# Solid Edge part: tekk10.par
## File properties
Author: Mac
Template: Normal.par
Last saved by: Mac
Revision: 42
Application: Solid Edge
Material: Epoxy, cast rigid
Face Style: White
Fill Style: ANSI34(Plastic)
Virtual Style: Shiny resin yellow
Coef. of Thermal Exp: 5.9e-05
Thermal Conductivity: 2.1
Specific Heat: 0.0
Modulus of Elasticity: 3102640650.0
Poission's Ratio: 0.37
Yield Stress: 65500191.5
Ultimate Stress: 0.0
Elongation: 0.0
Density: 1300,000 kg/m^3
Accuracy: 0,990
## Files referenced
..\Asm5.asm
AC:\Documents and Settings\Mac\Desktop\paat\Abi\paat abi1\Asm5.asm
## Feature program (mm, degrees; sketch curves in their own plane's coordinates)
sketch for "unnamed Protrusion 1" plane through (0, 0, 0) normal (0, 0, 1) x-axis (1, 0, 0)
  arc centre (-94.797, 27.5681) radius 7 from (-95.0745, 34.5626) to (-101.6037, 29.2016) ccw
  arc centre (18.0006, 0.4998) radius 123 from (-101.6037, 29.2016) to (-104.9983, 0) ccw
  line (105.0005, 0) -> (-104.9983, 0)
  line (105.0005, 0) -> (105.0005, 0.5)
extrude "unnamed Protrusion 1" add finite 5 along +normal
draft "Draft_6"  Angles1 = 15 deg
sketch for "ExtrudedProtrusion_6" plane through (0.0006, 17.2144, 5) normal (0, 0, 1) x-axis (1, 0, 0)
  line (-56.4794, 11.396) -> (-56.4794, 5.396)
  line (-56.5794, 5.396) -> (-56.4794, 5.396)
  line (-56.5794, 5.396) -> (-56.5794, 10.595)
  bspline degree 3 poles (-56.5794, 10.595) (-69.5519, 10.4638) (-83.3133, 10.0955) (-97.8592, 9.4888) knots 0 1 multiplicities 4 4
  arc centre (-97.8325, 8.8489) radius 0.6404 from (-97.8592, 9.4888) to (-98.4578, 8.9869) ccw
  arc centre (18.0001, -16.7146) radius 119.2603 from (-98.4578, 8.9869) to (-98.8901, 6.9432) ccw
  line (-98.8901, 6.9432) -> (-98.8901, -17.2144)
  line (-98.8901, -17.2144) -> (-100.2901, -17.2144)
  line (-100.2901, 7.083) -> (-100.2901, -17.2144)
  arc centre (18.0001, -16.7146) radius 120.6603 from (-99.8249, 9.2886) to (-100.2901, 7.083) ccw
  arc centre (-97.8325, 8.8489) radius 2.0404 from (-97.9175, 10.8875) to (-99.8249, 9.2886) ccw
  bspline degree 3 poles (32.7696, 7.7049) (18.6993, 9.6016) (2.4867, 10.8876) (-15.8311, 11.5412) (-39.6424, 12.3909) (-67.0155, 12.1765) (-97.9175, 10.8875) knots 0 0.9628 1 multiplicities 4 3 4
  bspline degree 3 poles (32.7696, 7.7049) (35.932, 0.931) (37.7314, -7.3754) (38.1682, -17.2144) knots 0 1 multiplicities 4 4
  line (38.1682, -17.2144) -> (10.8739, -17.2144)
  line (10.8739, 9.4225) -> (10.8739, -17.2144)
  bspline degree 3 poles (10.8739, 9.4225) (2.5339, 10.0961) (-6.3768, 10.6036) (-15.8526, 10.9417) (-28.4038, 11.3895) (-41.9478, 11.5415) (-56.4794, 11.396) knots 0 0.3128 1 multiplicities 4 3 4
extrude "ExtrudedProtrusion_6" add finite 1.4 along +normal
sketch for "unnamed Protrusion 2" plane through (-100.19, 0, 0) normal (1, 0, 0) x-axis (0, 1, 0)
  line (0.5, 0) -> (0.5, -11.1711)
  line (0.5, -11.1711) -> (24, -11.1711)
  line (24, -11.1711) -> (24, 0)
  line (24, 0) -> (0.5, 0)
extrude "unnamed Protrusion 2" add along +normal
sketch for "unnamed Protrusion 3" plane through (0, 0, 0) normal (0, -1, 0) x-axis (1, 0, 0)
  line (-100.19, 0) -> (-104.9994, 0)
  line (-100.19, -11.1711) -> (-110.0363, -11.1711)
  line (-100.19, 0) -> (-100.19, -11.1711)
extrude "unnamed Protrusion 3" add to key point along -normal
sketch for "ExtrudedProtrusion_13" plane through (0, 0, 0) normal (0, 0, 1) x-axis (1, 0, 0)
  arc centre (18.3803, 0.3808) radius 124.3034 from (-103.6585, 24) to (-102.7729, 28.1879) cw
  arc centre (-94.797, 27.5681) radius 8 from (-102.7729, 28.1879) to (-95.1142, 35.5618) cw
  arc centre (105.0005, 0) radius 1.2274 from (106.0979, 0.5496) to (106.2279, 0) cw
  line (106.2279, 0) -> (-99.6166, 0)
  line (-99.6166, 24) -> (-99.6166, 0)
  line (-99.6166, 24) -> (-103.6585, 24)
extrude "ExtrudedProtrusion_13" add finite 0.1 along +normal
sketch for "ExtrudedCutout_2" plane through (0, 0, 0) normal (0, -1, 0) x-axis (1, 0, 0)
  line (-109.752, 5) -> (-100.2896, 5)
  bspline degree 3 poles (-100.2896, 5) (-101.041, -0.6512) (-100.842, -5.6753) (-101.0728, -10.0711) knots 0 1 multiplicities 4 4
  line (-109.752, -10.0711) -> (-101.0728, -10.0711)
  line (-109.752, -10.0711) -> (-109.752, 5)
extrude "ExtrudedCutout_2" cut finite 22.9 along -normal
sketch for "ExtrudedProtrusion_16" plane through (-31.0604, 14.749, 6.4) normal (0, 0, 1) x-axis (0, 1, 0)
  bspline degree 3 poles (12.6794, 45.7982) (12.8671, 38.837) (12.994, 32.0769) (13.0603, 25.5184) knots 0 1 multiplicities 4 4
  line (13.0603, 25.5184) -> (7.8613, 25.5184)
  line (7.8613, 25.5184) -> (7.8613, 25.4184)
  line (7.8613, 25.4184) -> (13.8614, 25.4184)
  line (11.8878, -41.9348) -> (-14.749, -41.9348)
  line (-14.749, -41.9348) -> (-14.749, -69.2292)
  bspline degree 3 poles (10.0625, -63.8806) (11.9634, -49.7998) (13.2521, -33.569) (13.9066, -15.2263) (14.5579, 3.0262) (14.5839, 23.3727) (13.9798, 45.7982) knots 0 0.9746 1 multiplicities 4 3 4
  line (13.9798, 45.7982) -> (12.6794, 45.7982)
extrude "ExtrudedProtrusion_16" add finite 4 along +normal
draft "Draft_15"  Angles1 = 5 deg
draft "Draft_16"  Angles1 = 30 deg
lofted protrusion "unnamed LoftedProtrusion 1"
sketch for "unnamed Cutout 1" plane through (0, 0, 0) normal (0, 0, 1) x-axis (1, 0, 0)
  line (18.9219, 0) -> (82.9588, 0)
  line (82.9588, 0) -> (82.9588, -19.7583)
  line (18.9219, -19.7583) -> (82.9588, -19.7583)
  line (18.9219, 0) -> (18.9219, -19.7583)
extrude "unnamed Cutout 1" cut to key point along +normal
fillet "Round_5" radius 3.5
sketch for "unnamed Cutout 2" plane through (74.0361, 3, 6.9827) normal (0.330445, 0, 0.943825) x-axis (0.943825, 0, -0.330445)
extrude "unnamed Cutout 2" cut through along +normal
fillet "Round_6" radius 0.1
sketch for "ExtrudedProtrusion_17" plane through (-15.4502, 14.5146, 10.4) normal (0, 0, 1) x-axis (1, 0, 0)
extrude "ExtrudedProtrusion_17" add finite 1 along +normal
swept cutout "unnamed SweptCutout 1"
thinwall "unnamed Thinwall 1"
sketch for "unnamed Cutout 3" plane through (74.0588, 2.45, 6.9747) normal (0.330445, 0, 0.943825) x-axis (0.943825, 0, -0.330445)
extrude "unnamed Cutout 3" cut through along -normal
sketch for "ExtrudedProtrusion_18" plane through (-44.0075, 14.5811, 4.9) normal (0, 0, -1) x-axis (1, 0, 0)
extrude "ExtrudedProtrusion_18" add finite 11 along +normal
thinwall "unnamed Thinwall 2"
sketch for "unnamed Cutout 4" plane through (1.0405, 17.2144, 5) normal (0, 0, 1) x-axis (-1, 0, 0)
extrude "unnamed Cutout 4" cut through along -normal
sketch for "unnamed Protrusion 4" plane through (-56.5288, 25.2103, 5) normal (0, 0, -1) x-axis (0, 1, 0)
extrude "unnamed Protrusion 4" add along +normal
sketch for "unnamed Cutout 5" plane through (-44.0075, 14.806, -6) normal (0, 0, 1) x-axis (1, 0, 0)
extrude "unnamed Cutout 5" cut through along -normal
sketch for "unnamed Cutout 6" plane through (10.9745, 13.367, 2.6) normal (1, 0, 0) x-axis (0, 1, 0)
  line (15.0172, -8.7) -> (-14.9724, -8.7)
  line (-14.9724, 2.3) -> (-14.9724, -8.7)
  line (14.9833, 2.3) -> (-14.9724, 2.3)
  bspline degree 3 poles (14.9833, 2.3) (14.995, -1.3667) (15.0062, -5.0333) (15.0172, -8.7) knots 0 1 multiplicities 4 4
extrude "unnamed Cutout 6" cut along +normal
sketch for "unnamed Cutout 7" plane through (-8.4912, 14.3643, 11.4) normal (0, 0, 1) x-axis (1, 0, 0)
extrude "unnamed Cutout 7" cut to key point along -normal
body pattern "unnamed BodyPattern 1"
pattern "unnamed Pattern 1"
sketch for "unnamed Protrusion 5" plane through (-98.8896, 10.8081, 0.2) normal (1, 0, 0) x-axis (0, 1, 0)
extrude "unnamed Protrusion 5" add to key point along -normal
sketch for "unnamed Cutout 8" plane through (-98.8896, 0, 0.2) normal (1, 0, 0) x-axis (0, 0, -1)
extrude "unnamed Cutout 8" cut through along -normal
sketch for "ExtrudedCutout_20" plane through (0, 0, 0) normal (0, -1, 0) x-axis (1, 0, 0)
extrude "ExtrudedCutout_20" cut finite 16.0415 along +normal
fillet "Round_8" radius 0.1
sketch for "unnamed Cutout 9" plane through (-98.8896, -7, -6.15) normal (1, 0, 0) x-axis (0, -1, 0)
extrude "unnamed Cutout 9" cut to key point along -normal
thinwall "Thinwall_35"  Thickness = 0.1 mm
"unnamed Protrusion 6" has 27 sketches; the first 24 follow
sketch for "unnamed Protrusion 6" #1 plane through (-56.5788, 28.6678, 10.3) normal (-0.017704, 0.994034, 0.107628) x-axis (-0.982002, 0.002957, -0.188848)
extrude "unnamed Protrusion 6" add along -normal
"unnamed Protrusion 7" has 27 sketches; the first 24 follow
sketch for "unnamed Protrusion 7" #1 plane through (-76.8586, -28.7288, 6.4) normal (-0.012228, -0.996776, 0.079301) x-axis (0.981092, 0.003359, 0.193511)
extrude "unnamed Protrusion 7" add along -normal
sketch for "ExtrudedCutout_22" #1 plane through (-53.9233, 0, -6) normal (0, 0, 1) x-axis (0, 1, 0)
sketch for "ExtrudedCutout_22" #2 plane through (-53.9233, 0, -6) normal (0, 0, 1) x-axis (0, 1, 0)
sketch for "ExtrudedCutout_22" #3 plane through (-53.9233, 0, -6) normal (0, 0, 1) x-axis (0, 1, 0)
extrude "ExtrudedCutout_22" cut finite 0.01 along -normal
Other named dimensions: "KeypointCurve_10": StartDerivMagnitude = -43.6142 mm; EndDerivMagnitude = 43.6142 mm | "OffsetSurface_1": Distance = 0.1 mm | "ExtrudedSurface_1": FiniteDepth = 6 mm | "ExtrudedSurface_9": FiniteDepth = 85.0968 mm | "OffsetSurface_2": Distance = 0.01 mm | "OffsetSurface_3": Distance = 0.01 mm
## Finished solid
Body 1: sheet body, 1 face, 4 edges, 4 vertices.
  Faces by surface: offset 1
  Edges by curve: curve on surface 4
Body 2: sheet body, 1 face, 4 edges, 4 vertices.
  Faces by surface: offset 1
  Edges by curve: curve on surface 4
Body 3: sheet body, 1 face, 4 edges, 4 vertices.
  Faces by surface: plane 1
  Edges by curve: line 4
Body 4: sheet body, 1 face, 4 edges, 4 vertices.
  Faces by surface: plane 1
  Edges by curve: line 4
Body 5: sheet body, 1 face, 4 edges, 4 vertices.
  Faces by surface: offset 1
  Edges by curve: curve on surface 4
Body 6: sheet body, 1 face, 4 edges, 4 vertices.
  Faces by surface: spline 1
  Edges by curve: spline 3, circle 1
Body 7: solid body, 901 faces, 2466 edges, 1629 vertices.
  Faces by surface: plane 457, swept 261, offset 79, cylinder 50, blend 24, spline 22, cone 8
  Edges by curve: intersection 1286, line 972, circle 108, spline 56, curve on surface 32, ellipse 12
Bounding box of the edges (mm; curved faces can reach further): 218.616 x 85.097 x 51.944, from (-112.3877, -42.5484, -36.2684) to (106.2279, 42.5484, 15.6751).
Cylindrical faces by radius (mm): R0.08 x6, R0.1 x15, R0.2 x8, R0.6404 x2, R0.7404 x2, R1.2274 x1, R1.9404 x2, R2.0404 x2, R8 x2, R119.2603 x2, R119.3603 x2, R120.5603 x2, R120.6603 x2, R124.3034 x2
Conical faces (half-angle, radius in mm at the cone's reference point): 15 deg R6.9034 x2, 15 deg R7 x2, 15 deg R122.9034 x2, 15 deg R123 x2
Planar faces by outward normal: +x 14, +y 10, +z 13, -x 15, -y 13, -z 13, oblique 379
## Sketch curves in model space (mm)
line (42.4934, 0.0256, 11.4) -> (39.6089, -0.2079, 11.4)
line (42.4934, 0.0256, 11.4) -> (42.4934, 0.0256, 10.4)
line (42.4934, 0.0256, 10.4) -> (40.7983, -0.1116, 10.4)
arc centre (-47.5053, -7.2589, -94.1029) radius 137.0017 from (40.7983, -0.1116, 10.4) through (40.205, -0.1596, 10.9017) to (39.6089, -0.2079, 11.4)
line (-7.0908, 0, -7.0432) -> (-5.1033, 0, 15.6751)
spline (99.31, 7.1, 2.55) -> (36.2531, 30.1455, 2.55) -> (-56.5831, 34.8661, 2.55)
spline (39.8441, -0.1888, 11.4) -> (36.7349, 14.4668, 11.4) -> (30.3607, 24.681, 11.4)
line (-86.4757, 0, -12.1697) -> (102.5777, 0, -23.8321)
line (84.448, 0, 42.5362) -> (77.6507, 0, -43.2576)
line (-21.5, 0, 50.9303) -> (-28.2973, 0, -34.8635)
line (79.6991, 0, 5) -> (68.3732, 0, 8.9653)
arc centre (69.4492, -4.3, 8.5886) radius 0.2 from (69.4492, -4.5, 8.5886) through (69.3119, -4.4372, 8.6367) to (69.2604, -4.3, 8.6547)
line (77.6848, -4.5, 5.7052) -> (69.4492, -4.5, 8.5886)
arc centre (77.6848, -4.3, 5.7052) radius 0.2 from (77.8736, -4.3, 5.6391) through (77.8143, -4.4455, 5.6599) to (77.6848, -4.5, 5.7052)
line (77.8736, -4.3, 5.6391) -> (77.8736, 4.3, 5.6391)
arc centre (77.6848, 4.3, 5.7052) radius 0.2 from (77.8736, 4.3, 5.6391) through (77.8143, 4.4455, 5.6599) to (77.6848, 4.5, 5.7052)
line (77.6848, 4.5, 5.7052) -> (69.4492, 4.5, 8.5886)
arc centre (69.4492, 4.3, 8.5886) radius 0.2 from (69.4492, 4.5, 8.5886) through (69.3119, 4.4372, 8.6367) to (69.2604, 4.3, 8.6547)
line (69.2604, 4.3, 8.6547) -> (69.2604, -4.3, 8.6547)
spline (79.6991, 0, 5) -> (68.5758, -0.2796, 8.9354) -> (37.2044, -1.068, 10.4)
line (37.2044, -1.068, 10.4) -> (37.2044, -1.068, 5)
line (37.2044, -1.068, 5) -> (79.6991, 0, 5)
line (32.7701, 24.9192, 6.4) -> (32.7701, 24.9192, 5)
spline (32.7701, 24.9192, 5) -> (32.2097, 21.3193, 9.2031) -> (29.5886, 4.4839, 10.373)
line (29.5886, 4.4839, 10.373) -> (29.5886, 4.4839, 5)
line (32.7701, 24.9192, 5) -> (29.5886, 4.4839, 5)
spline (32.7701, 24.9192, 5) -> (65.0356, 16.1294, 5) -> (79.6991, 0, 5)
line (106.2279, 0, 0) -> (-99.6166, 0, 0)
arc centre (105.0005, 0, 0) radius 1.2274 from (106.0979, 0.5496, 0) through (106.1949, 0.2824, 0) to (106.2279, 0, 0)
spline (-95.1142, 35.5618, 0) -> (30.0728, 32.6689, 0) -> (106.0979, 0.5496, 0)
arc centre (-94.797, 27.5681, 0) radius 8 from (-102.7729, 28.1879, 0) through (-100.1758, 33.49, 0) to (-95.1142, 35.5618, 0)
arc centre (18.3803, 0.3808, 0) radius 124.3034 from (-103.6585, 24, 0) through (-103.2338, 26.0978, 0) to (-102.7729, 28.1879, 0)
line (-99.6166, 24, 0) -> (-103.6585, 24, 0)
line (-99.6166, 24, 0) -> (-99.6166, 0, 0)
line (-100.19, 23, -0.0414) -> (-100.19, 23, -10.1711)
spline (-100.19, 24, -0.0404) -> (-100.19, 23.5002, -0.0409) -> (-100.19, 23, -0.0414)
line (-100.19, 24, -11.1711) -> (-100.19, 24, -0.0404)
line (-100.19, 0.5, -11.1711) -> (-100.19, 24, -11.1711)
line (-100.19, 0.5, -10.1711) -> (-100.19, 0.5, -11.1711)
line (-100.19, 0.5, -10.1711) -> (-100.19, 23, -10.1711)
line (-100.19, 24, -11.1711) -> (-100.19, 24, 0)
line (-100.19, 24, 0) -> (-100.19, 0.5, 0)
line (-100.19, 0.5, 0) -> (-100.19, 0.5, -11.1711)
line (-100.19, 0.5, -11.1711) -> (-100.19, 24, -11.1711)
line (10.8745, 26.6368, 5) -> (10.8745, 0, 5)
spline (10.8745, 26.6368, 5) -> (-26.3292, 28.4561, 5) -> (-56.4788, 28.6104, 5)
line (-56.4788, 28.6104, 5) -> (-56.4788, 22.6104, 5)
line (-56.5788, 22.6104, 5) -> (-56.4788, 22.6104, 5)
line (-56.5788, 22.6104, 5) -> (-56.5788, 27.8093, 5)
spline (-56.5788, 27.8093, 5) -> (-76.6287, 27.4346, 5) -> (-97.8586, 26.7031, 5)
arc centre (-97.8319, 26.0633, 5) radius 0.6404 from (-97.8586, 26.7031, 5) through (-98.2433, 26.5541, 5) to (-98.4572, 26.2013, 5)
arc centre (18.0006, 0.4998, 5) radius 119.2603 from (-98.4572, 26.2013, 5) through (-98.6779, 25.1804, 5) to (-98.8896, 24.1575, 5)
line (-98.8896, 24.1575, 5) -> (-98.8896, 0, 5)
line (-98.8896, 0, 5) -> (-100.2896, 0, 5)
line (-100.2896, 24.2974, 5) -> (-100.2896, 0, 5)
arc centre (18.0006, 0.4998, 5) radius 120.6603 from (-99.8243, 26.503, 5) through (-100.0621, 25.4013, 5) to (-100.2896, 24.2974, 5)
arc centre (-97.8319, 26.0633, 5) radius 2.0404 from (-97.9169, 28.1019, 5) through (-99.1427, 27.627, 5) to (-99.8243, 26.503, 5)
spline (32.7701, 24.9192, 5) -> (9.1204, 27.3772, 5) -> (-97.9169, 28.1019, 5)
spline (32.7701, 24.9192, 5) -> (36.4915, 13.609, 5) -> (38.1688, 0, 5)
line (38.1688, 0, 5) -> (10.8745, 0, 5)
spline (-110.7878, 30.7782, -24.5324) -> (-28.564, 29.4368, -24.5324) -> (52.4813, 16.4919, -24.5324)
spline (-104.9994, 0.5, 0) -> (-110.542, 0.5, -13.4256) -> (-112.3877, 0.5, -36.2684)
arc centre (18.0006, 0.4998, 0) radius 123 from (-101.6037, 29.2016, 0) through (-104.1475, 14.9509, 0) to (-104.9994, 0.5, 0)
line (105.0005, 0, 0) -> (-104.9983, 0, 0)
line (105.0005, 0, 0) -> (105.0005, 0.5, 0)
spline (105.0005, 0.5, 0) -> (44.2326, 29.5896, 0) -> (-95.0745, 34.5626, 0)
arc centre (-94.797, 27.5681, 0) radius 7 from (-95.0745, 34.5626, 0) through (-99.2391, 32.9781, 0) to (-101.6037, 29.2016, 0)
arc centre (18.0006, 0.4998, 0) radius 123 from (-101.6037, 29.2016, 0) through (-104.1766, 14.7026, 0) to (-104.9983, 0, 0)
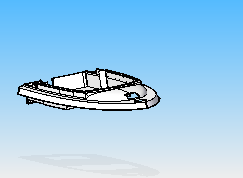
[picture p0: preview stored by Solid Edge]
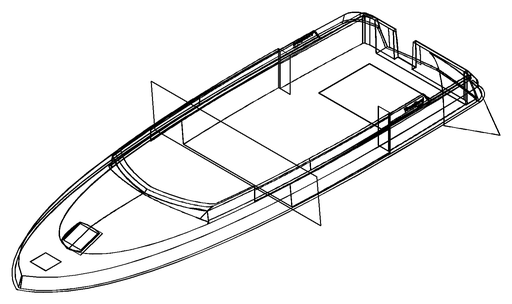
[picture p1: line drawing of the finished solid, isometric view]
